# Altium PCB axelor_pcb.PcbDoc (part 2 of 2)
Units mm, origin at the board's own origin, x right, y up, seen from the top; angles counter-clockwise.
Board outline 74.68 x 44.83 mm, 4 copper layers (Top Layer, Int1 (GND), Int2 (PWR), Bottom Layer), stack 1.586 mm thick; 281 components, 64 nets, 713 pads, 300 vias.
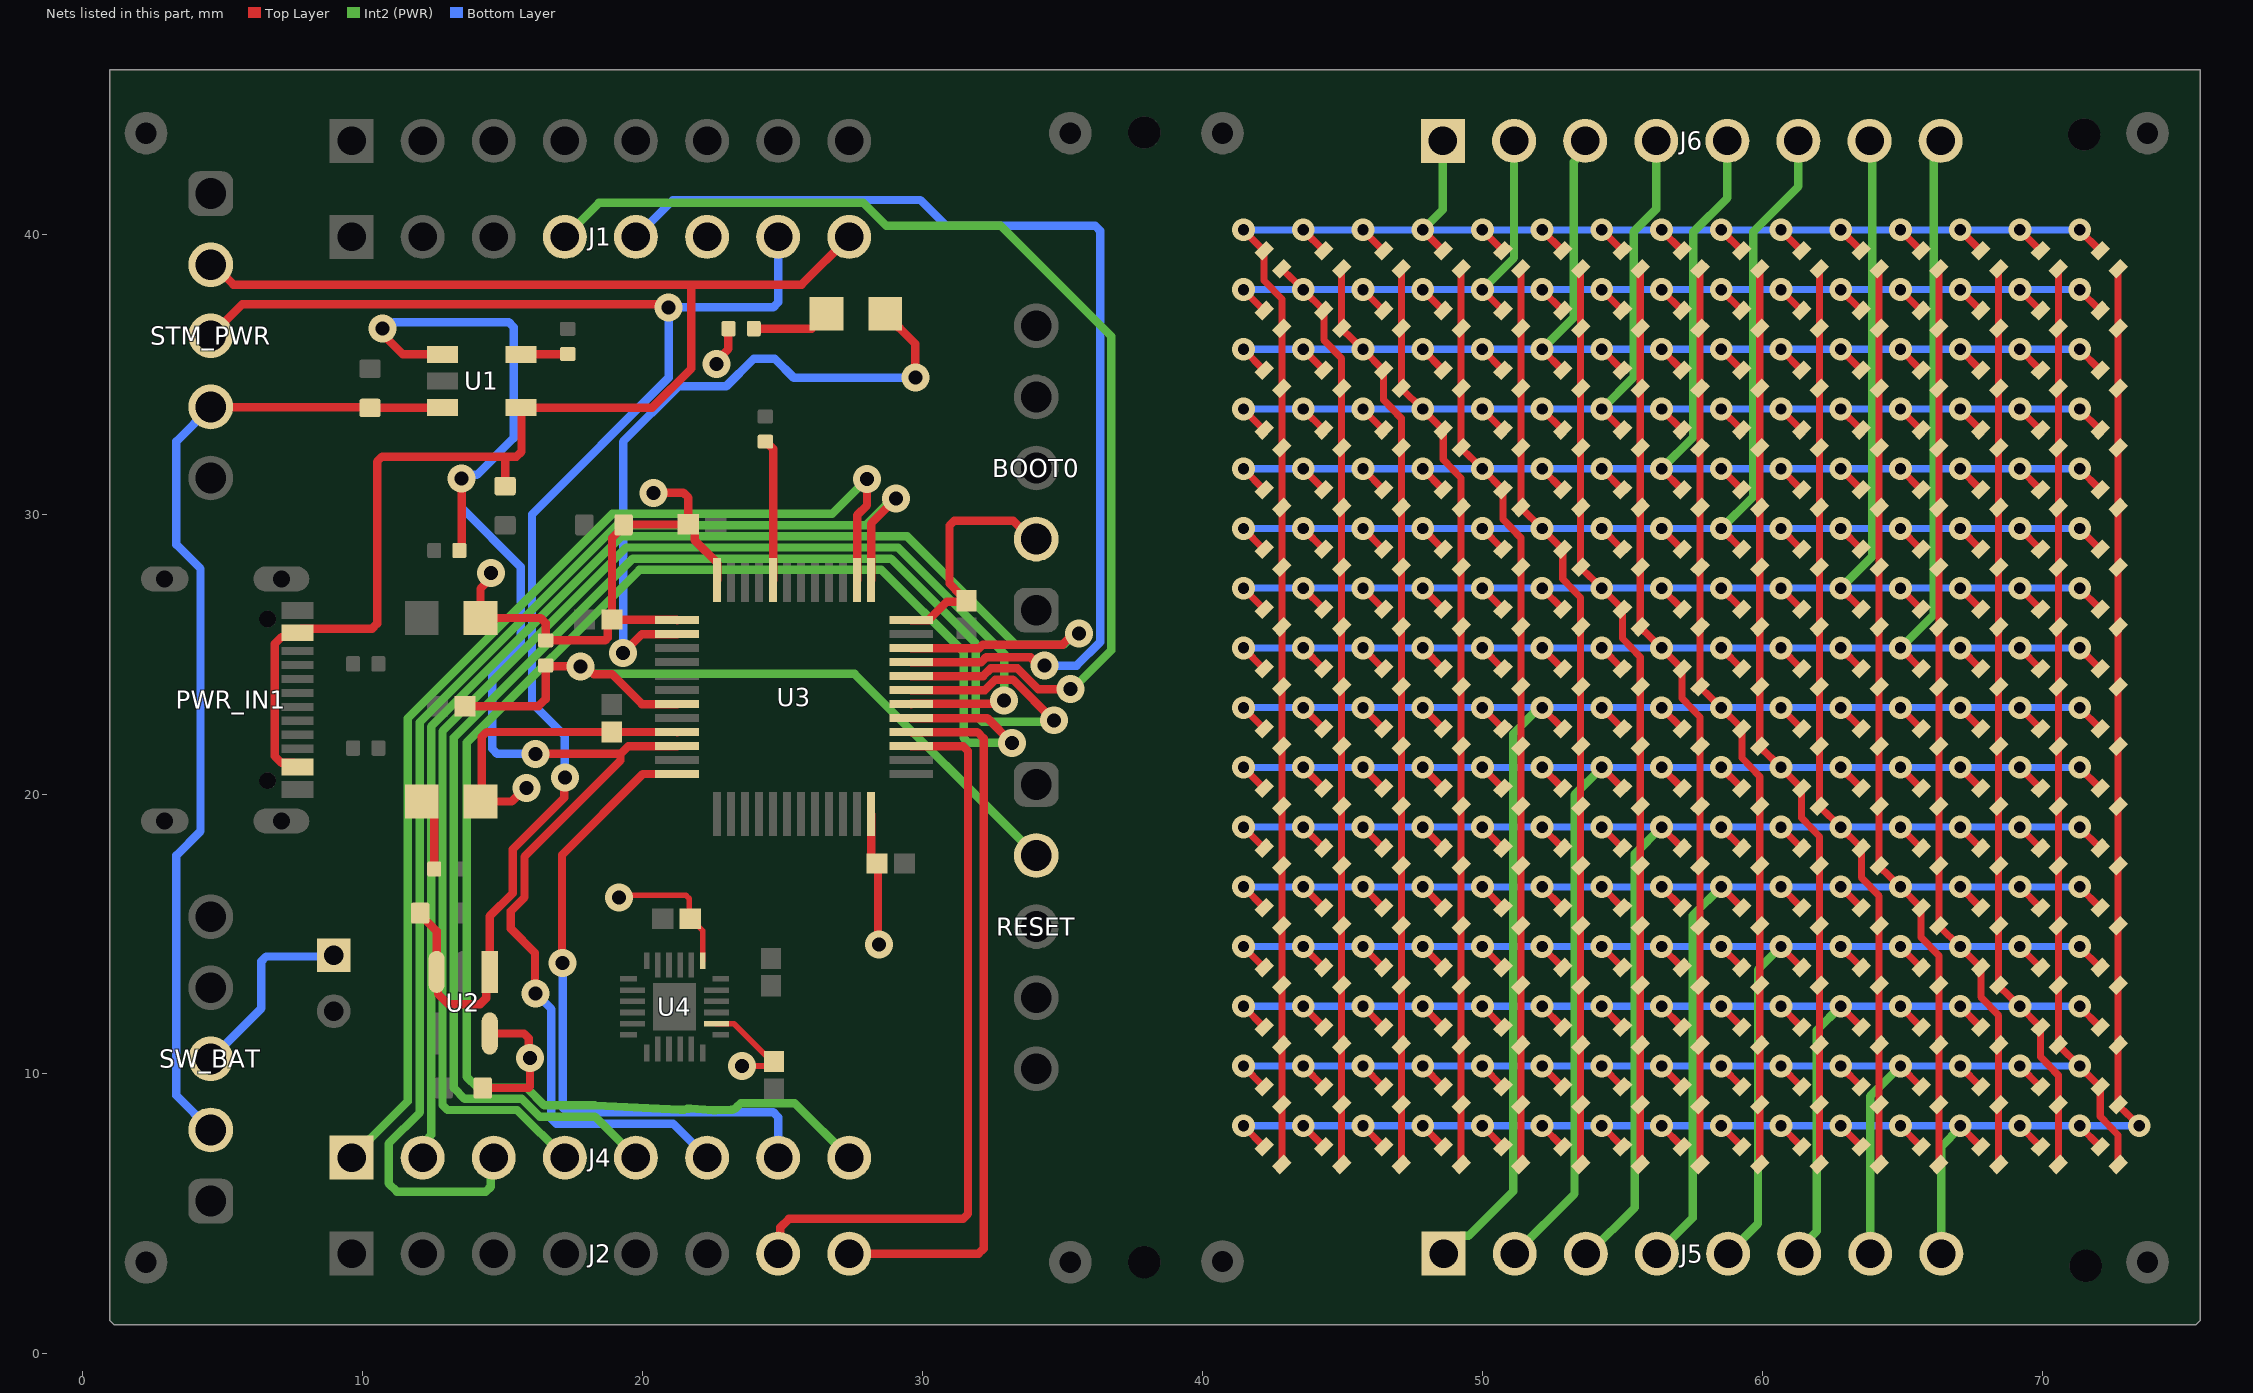
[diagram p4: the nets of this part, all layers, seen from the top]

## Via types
v1: diameter 0.813, hole 0.406, Top Layer to Bottom Layer, 241 vias
v2: diameter 1, hole 0.5, Top Layer to Bottom Layer, 55 vias
v3: diameter 0.5, hole 0.2, Top Layer to Bottom Layer, 4 vias

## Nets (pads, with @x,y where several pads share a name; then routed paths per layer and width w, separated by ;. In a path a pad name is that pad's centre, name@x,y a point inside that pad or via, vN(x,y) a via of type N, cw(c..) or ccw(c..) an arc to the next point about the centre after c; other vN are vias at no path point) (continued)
PB14: J2.7 U3.27 | length 26.5
  Top Layer w0.3: J2.7@24.841,3.581 24.917,3.658 24.917,4.521 25.222,4.826 31.447,4.826 31.623,5.002 31.623,21.54 31.447,21.716 U3.27@29.591,21.716
PB15: J2.8 U3.28 | length 25.8
  Top Layer w0.3: J2.8@27.381,3.581 32.006,3.581 32.182,3.757 32.182,21.99 31.956,22.216 U3.28@29.591,22.216
PIN1: D1.1 D2.1 D3.1 D4.1 D5.1 D6.1 D7.1 D8.1 D9.1 D10.1 D11.1 D12.1 D13.1 D14.1 D15.1 D16.2 D31.2 D46.2 D61.2 D76.2 D91.2 D106.2 D121.2 D136.2 D151.2 D166.2 D181.2 D196.2 D211.2 D226.2 J6.1 | length 81.9
  Top Layer w0.254: v1@41.465,40.145 D1.1@42.202,39.408 ; D1.1@42.202,39.42 42.202,38.353 42.838,37.693 D16.2@42.838,36.638 D31.2@42.838,34.505 D46.2@42.838,32.371 D61.2@42.838,30.237 D76.2@42.838,28.104 D91.2@42.838,25.97 D106.2@42.838,23.837 D121.2@42.838,21.703 D136.2@42.838,19.569 D151.2@42.838,17.436 D166.2@42.838,15.302 D181.2@42.838,13.169 D196.2@42.838,11.035 D211.2@42.838,8.901 D226.2@42.838,6.756 ; v1@43.599,40.145 D2.1@44.336,39.408 ; v1@45.733,40.145 D3.1@46.469,39.408 ; v1@47.866,40.145 D4.1@48.603,39.408 ; v1@50,40.145 D5.1@50.736,39.408 ; v1@52.133,40.145 D6.1@52.87,39.408 ; v1@54.267,40.145 D7.1@55.004,39.408 ; v1@56.401,40.145 D8.1@57.137,39.408 ; v1@58.534,40.145 D9.1@59.271,39.408 ; v1@60.668,40.145 D10.1@61.404,39.408 ; v1@62.801,40.145 D11.1@63.538,39.408 ; v1@64.935,40.145 D12.1@65.672,39.408 ; v1@67.069,40.145 D13.1@67.805,39.408 ; v1@69.202,40.145 D14.1@69.939,39.408 ; v1@71.336,40.145 D15.1@72.072,39.408
  Int2 (PWR) w0.3: v1(47.866,40.157) 48.59,40.881 J6.1@48.59,43.332
  Bottom Layer w0.254: v1(41.465,40.157) v1(43.599,40.157) v1(45.733,40.157) v1(47.866,40.157) v1(50,40.157) v1(52.133,40.157) v1(54.267,40.157) v1(56.401,40.157) v1(58.534,40.157) v1(60.668,40.157) v1(62.801,40.157) v1(64.935,40.157) v1(67.069,40.157) v1(69.202,40.157) v1(71.336,40.157)
PIN2: D1.2 D16.1 D17.1 D18.1 D19.1 D20.1 D21.1 D22.1 D23.1 D24.1 D25.1 D26.1 D27.1 D28.1 D29.1 D30.1 D32.2 D47.2 D62.2 D77.2 D92.2 D107.2 D122.2 D137.2 D152.2 D167.2 D182.2 D197.2 D212.2 D227.2 J6.2 | length 83.1
  Top Layer w0.254: v1@41.465,38.011 D16.1@42.202,37.274 ; D1.2@42.838,38.76 v1(43.599,38.023) ; v1@43.599,38.011 D17.1@44.336,37.274 ; D17.1@44.336,37.287 44.336,36.22 44.972,35.559 D32.2@44.972,34.505 D47.2@44.972,32.371 D62.2@44.972,30.237 D77.2@44.972,28.104 D92.2@44.972,25.97 D107.2@44.972,23.837 D122.2@44.972,21.703 D137.2@44.972,19.569 D152.2@44.972,17.436 D167.2@44.972,15.302 D182.2@44.972,13.169 D197.2@44.972,11.035 D212.2@44.972,8.901 D227.2@44.972,6.756 ; v1@45.733,38.011 D18.1@46.469,37.274 ; v1@47.866,38.011 D19.1@48.603,37.274 ; v1@50,38.011 D20.1@50.736,37.274 ; v1@52.133,38.011 D21.1@52.87,37.274 ; v1@54.267,38.011 D22.1@55.004,37.274 ; v1@56.401,38.011 D23.1@57.137,37.274 ; v1@58.534,38.011 D24.1@59.271,37.274 ; v1@60.668,38.011 D25.1@61.404,37.274 ; v1@62.801,38.011 D26.1@63.538,37.274 ; v1@64.935,38.011 D27.1@65.672,37.274 ; v1@67.069,38.011 D28.1@67.805,37.274 ; v1@69.202,38.011 D29.1@69.939,37.274 ; v1@71.336,38.011 D30.1@72.072,37.274
  Int2 (PWR) w0.3: v1(50,38.023) 51.13,39.153 J6.2@51.13,43.332
  Bottom Layer w0.254: v1(41.465,38.023) v1(43.599,38.023) v1(45.733,38.023) v1(47.866,38.023) v1(50,38.023) v1(52.133,38.023) v1(54.267,38.023) v1(56.401,38.023) v1(58.534,38.023) v1(60.668,38.023) v1(62.801,38.023) v1(64.935,38.023) v1(67.069,38.023) v1(69.202,38.023) v1(71.336,38.023)
PIN3: D2.2 D17.2 D31.1 D32.1 D33.1 D34.1 D35.1 D36.1 D37.1 D38.1 D39.1 D40.1 D41.1 D42.1 D43.1 D44.1 D45.1 D48.2 D63.2 D78.2 D93.2 D108.2 D123.2 D138.2 D153.2 D168.2 D183.2 D198.2 D213.2 D228.2 J6.3 | length 85.5
  Top Layer w0.254: v1@41.465,35.877 D31.1@42.202,35.141 ; v1@43.599,35.877 D32.1@44.336,35.141 ; D2.2@44.972,38.76 44.972,36.626 v1(45.733,35.89) ; v1@45.733,35.877 D33.1@46.469,35.141 ; D33.1@46.469,35.153 46.469,34.086 47.106,33.426 D48.2@47.106,32.371 D63.2@47.106,30.237 D78.2@47.106,28.104 D93.2@47.106,25.97 D108.2@47.106,23.837 D123.2@47.106,21.703 D138.2@47.106,19.569 D153.2@47.106,17.436 D168.2@47.106,15.302 D183.2@47.106,13.169 D198.2@47.106,11.035 D213.2@47.106,8.901 D228.2@47.106,6.756 ; v1@47.866,35.877 D34.1@48.603,35.141 ; v1@50,35.877 D35.1@50.736,35.141 ; v1@52.133,35.877 D36.1@52.87,35.141 ; v1@54.267,35.877 D37.1@55.004,35.141 ; v1@56.401,35.877 D38.1@57.137,35.141 ; v1@58.534,35.877 D39.1@59.271,35.141 ; v1@60.668,35.877 D40.1@61.404,35.141 ; v1@62.801,35.877 D41.1@63.538,35.141 ; v1@64.935,35.877 D42.1@65.672,35.141 ; v1@67.069,35.877 D43.1@67.805,35.141 ; v1@69.202,35.877 D44.1@69.939,35.141 ; v1@71.336,35.877 D45.1@72.072,35.141
  Int2 (PWR) w0.3: v1@41.389,35.966 v1(41.465,35.89) ; v1(52.133,35.89) 53.262,37.018 53.262,42.58 53.67,42.989 J6.3@53.67,43.332
  Bottom Layer w0.254: v1(41.465,35.89) v1(43.599,35.89) v1(45.733,35.89) v1(47.866,35.89) v1(50,35.89) v1(52.133,35.89) v1(54.267,35.89) v1(56.401,35.89) v1(58.534,35.89) v1(60.668,35.89) v1(62.801,35.89) v1(64.935,35.89) v1(67.069,35.89) v1(69.202,35.89) v1(71.336,35.89)
PIN4: D3.2 D18.2 D33.2 D46.1 D47.1 D48.1 D49.1 D50.1 D51.1 D52.1 D53.1 D54.1 D55.1 D56.1 D57.1 D58.1 D59.1 D60.1 D64.2 D79.2 D94.2 D109.2 D124.2 D139.2 D154.2 D169.2 D184.2 D199.2 D214.2 D229.2 J6.4 | length 87.7
  Top Layer w0.254: v1@41.465,33.744 D46.1@42.202,33.007 ; v1@43.599,33.744 D47.1@44.336,33.007 ; v1@45.733,33.744 D48.1@46.469,33.007 ; D3.2@47.106,38.76 D18.2@47.106,36.638 47.106,34.493 v1(47.866,33.756) ; v1@47.866,33.744 D49.1@48.603,33.007 ; D49.1@48.603,33.019 48.603,31.953 49.239,31.292 D64.2@49.239,30.237 D79.2@49.239,28.104 D94.2@49.239,25.97 D109.2@49.239,23.837 D124.2@49.239,21.703 D139.2@49.239,19.569 D154.2@49.239,17.436 D169.2@49.239,15.302 D184.2@49.239,13.169 D199.2@49.239,11.035 D214.2@49.239,8.901 D229.2@49.239,6.756 ; v1@50,33.744 D50.1@50.736,33.007 ; v1@52.133,33.744 D51.1@52.87,33.007 ; v1@54.267,33.744 D52.1@55.004,33.007 ; v1@56.401,33.744 D53.1@57.137,33.007 ; v1@58.534,33.744 D54.1@59.271,33.007 ; v1@60.668,33.744 D55.1@61.404,33.007 ; v1@62.801,33.744 D56.1@63.538,33.007 ; v1@64.935,33.744 D57.1@65.672,33.007 ; v1@67.069,33.744 D58.1@67.805,33.007 ; v1@69.202,33.744 D59.1@69.939,33.007 ; v1@71.336,33.744 D60.1@72.072,33.007
  Int2 (PWR) w0.3: v1(54.267,33.756) 55.407,34.896 55.407,40.091 56.21,40.894 J6.4@56.21,43.332
  Bottom Layer w0.254: v1(41.465,33.756) v1(43.599,33.756) v1(45.733,33.756) v1(47.866,33.756) v1(50,33.756) v1(52.133,33.756) v1(54.267,33.756) v1(56.401,33.756) v1(58.534,33.756) v1(60.668,33.756) v1(62.801,33.756) v1(64.935,33.756) v1(67.069,33.756) v1(69.202,33.756) v1(71.336,33.756)
PIN5: D4.2 D19.2 D34.2 D49.2 D61.1 D62.1 D63.1 D64.1 D65.1 D66.1 D67.1 D68.1 D69.1 D70.1 D71.1 D72.1 D73.1 D74.1 D75.1 D80.2 D95.2 D110.2 D125.2 D140.2 D155.2 D170.2 D185.2 D200.2 D215.2 D230.2 J6.5 | length 90
  Top Layer w0.254: v1@41.465,31.61 D61.1@42.202,30.874 ; v1@43.599,31.61 D62.1@44.336,30.874 ; v1@45.733,31.61 D63.1@46.469,30.874 ; v1@47.866,31.61 D64.1@48.603,30.874 ; D4.2@49.239,38.76 D19.2@49.239,36.638 D34.2@49.239,34.505 49.239,32.359 v1(50,31.622) ; v1@50,31.61 D65.1@50.736,30.874 ; D65.1@50.736,30.886 50.736,29.819 51.373,29.159 D80.2@51.373,28.104 D95.2@51.373,25.97 D110.2@51.373,23.837 D125.2@51.373,21.703 D140.2@51.373,19.569 D155.2@51.373,17.436 D170.2@51.373,15.302 D185.2@51.373,13.169 D200.2@51.373,11.035 D215.2@51.373,8.901 D230.2@51.373,6.756 ; v1@52.133,31.61 D66.1@52.87,30.874 ; v1@54.267,31.61 D67.1@55.004,30.874 ; v1@56.401,31.61 D68.1@57.137,30.874 ; v1@58.534,31.61 D69.1@59.271,30.874 ; v1@60.668,31.61 D70.1@61.404,30.874 ; v1@62.801,31.61 D71.1@63.538,30.874 ; v1@64.935,31.61 D72.1@65.672,30.874 ; v1@67.069,31.61 D73.1@67.805,30.874 ; v1@69.202,31.61 D74.1@69.939,30.874 ; v1@71.336,31.61 D75.1@72.072,30.874
  Int2 (PWR) w0.3: v1(56.401,31.622) 57.538,32.76 57.538,40.089 58.75,41.301 J6.5@58.75,43.332
  Bottom Layer w0.254: v1(41.465,31.622) v1(43.599,31.622) v1(45.733,31.622) v1(47.866,31.622) v1(50,31.622) v1(52.133,31.622) v1(54.267,31.622) v1(56.401,31.622) v1(58.534,31.622) v1(60.668,31.622) v1(62.801,31.622) v1(64.935,31.622) v1(67.069,31.622) v1(69.202,31.622) v1(71.336,31.622)
PIN6: D5.2 D20.2 D35.2 D50.2 D65.2 D76.1 D77.1 D78.1 D79.1 D80.1 D81.1 D82.1 D83.1 D84.1 D85.1 D86.1 D87.1 D88.1 D89.1 D90.1 D96.2 D111.2 D126.2 D141.2 D156.2 D171.2 D186.2 D201.2 D216.2 D231.2 J6.6 | length 92.3
  Top Layer w0.254: v1@41.465,29.477 D76.1@42.202,28.74 ; v1@43.599,29.477 D77.1@44.336,28.74 ; v1@45.733,29.477 D78.1@46.469,28.74 ; v1@47.866,29.477 D79.1@48.603,28.74 ; v1@50,29.477 D80.1@50.736,28.74 ; D5.2@51.373,38.76 D20.2@51.373,36.638 D35.2@51.373,34.505 D50.2@51.373,32.371 51.373,30.225 v1(52.133,29.489) ; v1@52.133,29.477 D81.1@52.87,28.74 ; D81.1@52.87,28.752 52.87,27.685 53.506,27.025 D96.2@53.506,25.97 D111.2@53.506,23.837 D126.2@53.506,21.703 D141.2@53.506,19.569 D156.2@53.506,17.436 D171.2@53.506,15.302 D186.2@53.506,13.169 D201.2@53.506,11.035 D216.2@53.506,8.901 D231.2@53.506,6.756 ; v1@54.267,29.477 D82.1@55.004,28.74 ; v1@56.401,29.477 D83.1@57.137,28.74 ; v1@58.534,29.477 D84.1@59.271,28.74 ; v1@60.668,29.477 D85.1@61.404,28.74 ; v1@62.801,29.477 D86.1@63.538,28.74 ; v1@64.935,29.477 D87.1@65.672,28.74 ; v1@67.069,29.477 D88.1@67.805,28.74 ; v1@69.202,29.477 D89.1@69.939,28.74 ; v1@71.336,29.477 D90.1@72.072,28.74
  Int2 (PWR) w0.3: v1(58.534,29.489) 59.678,30.632 59.678,40.095 61.29,41.707 J6.6@61.29,43.332
  Bottom Layer w0.254: v1(41.465,29.489) v1(43.599,29.489) v1(45.733,29.489) v1(47.866,29.489) v1(50,29.489) v1(52.133,29.489) v1(54.267,29.489) v1(56.401,29.489) v1(58.534,29.489) v1(60.668,29.489) v1(62.801,29.489) v1(64.935,29.489) v1(67.069,29.489) v1(69.202,29.489) v1(71.336,29.489)
PIN7: D6.2 D21.2 D36.2 D51.2 D66.2 D81.2 D91.1 D92.1 D93.1 D94.1 D95.1 D96.1 D97.1 D98.1 D99.1 D100.1 D101.1 D102.1 D103.1 D104.1 D105.1 D112.2 D127.2 D142.2 D157.2 D172.2 D187.2 D202.2 D217.2 D232.2 J6.7 | length 93.8
  Top Layer w0.254: v1@41.465,27.343 D91.1@42.202,26.607 ; v1@43.599,27.343 D92.1@44.336,26.607 ; v1@45.733,27.343 D93.1@46.469,26.607 ; v1@47.866,27.343 D94.1@48.603,26.607 ; v1@50,27.343 D95.1@50.736,26.607 ; v1@52.133,27.343 D96.1@52.87,26.607 ; D6.2@53.506,38.76 D21.2@53.506,36.638 D36.2@53.506,34.505 D51.2@53.506,32.371 D66.2@53.506,30.237 53.506,28.092 v1(54.267,27.355) ; v1@54.267,27.343 D97.1@55.004,26.607 ; D97.1@55.004,26.619 55.004,25.552 55.64,24.891 D112.2@55.64,23.837 D127.2@55.64,21.703 D142.2@55.64,19.569 D157.2@55.64,17.436 D172.2@55.64,15.302 D187.2@55.64,13.169 D202.2@55.64,11.035 D217.2@55.64,8.901 D232.2@55.64,6.756 ; v1@56.401,27.343 D98.1@57.137,26.607 ; v1@58.534,27.343 D99.1@59.271,26.607 ; v1@60.668,27.343 D100.1@61.404,26.607 ; v1@62.801,27.343 D101.1@63.538,26.607 ; v1@64.935,27.343 D102.1@65.672,26.607 ; v1@67.069,27.343 D103.1@67.805,26.607 ; v1@69.202,27.343 D104.1@69.939,26.607 ; v1@71.336,27.343 D105.1@72.072,26.607
  Int2 (PWR) w0.3: v1(62.801,27.355) 63.925,28.479 63.925,43.237 J6.7@63.83,43.332
  Bottom Layer w0.254: v1(41.465,27.355) v1(43.599,27.355) v1(45.733,27.355) v1(47.866,27.355) v1(50,27.355) v1(52.133,27.355) v1(54.267,27.355) v1(56.401,27.355) v1(58.534,27.355) v1(60.668,27.355) v1(62.801,27.355) v1(64.935,27.355) v1(67.069,27.355) v1(69.202,27.355) v1(71.336,27.355)
PIN8: D7.2 D22.2 D37.2 D52.2 D67.2 D82.2 D97.2 D106.1 D107.1 D108.1 D109.1 D110.1 D111.1 D112.1 D113.1 D114.1 D115.1 D116.1 D117.1 D118.1 D119.1 D120.1 D128.2 D143.2 D158.2 D173.2 D188.2 D203.2 D218.2 D233.2 J6.8 | length 96
  Top Layer w0.254: v1@41.465,25.209 D106.1@42.202,24.473 ; v1@43.599,25.209 D107.1@44.336,24.473 ; v1@45.733,25.209 D108.1@46.469,24.473 ; v1@47.866,25.209 D109.1@48.603,24.473 ; v1@50,25.209 D110.1@50.736,24.473 ; v1@52.133,25.209 D111.1@52.87,24.473 ; v1@54.267,25.209 D112.1@55.004,24.473 ; D7.2@55.64,38.76 D22.2@55.64,36.638 D37.2@55.64,34.505 D52.2@55.64,32.371 D67.2@55.64,30.237 D82.2@55.64,28.104 55.64,25.958 v1(56.401,25.222) ; v1@56.401,25.209 D113.1@57.137,24.473 ; D113.1@57.137,24.485 57.137,23.418 57.774,22.758 D128.2@57.774,21.703 D143.2@57.774,19.569 D158.2@57.774,17.436 D173.2@57.774,15.302 D188.2@57.774,13.169 D203.2@57.774,11.035 D218.2@57.774,8.901 D233.2@57.774,6.756 ; v1@58.534,25.209 D114.1@59.271,24.473 ; v1@60.668,25.209 D115.1@61.404,24.473 ; v1@62.801,25.209 D116.1@63.538,24.473 ; v1@64.935,25.209 D117.1@65.672,24.473 ; v1@67.069,25.209 D118.1@67.805,24.473 ; v1@69.202,25.209 D119.1@69.939,24.473 ; v1@71.336,25.209 D120.1@72.072,24.473
  Int2 (PWR) w0.3: v1(64.935,25.222) 66.127,26.414 66.127,43.089 J6.8@66.37,43.332
  Bottom Layer w0.254: v1(41.465,25.222) v1(43.599,25.222) v1(45.733,25.222) v1(47.866,25.222) v1(50,25.222) v1(52.133,25.222) v1(54.267,25.222) v1(56.401,25.222) v1(58.534,25.222) v1(60.668,25.222) v1(62.801,25.222) v1(64.935,25.222) v1(67.069,25.222) v1(69.202,25.222) v1(71.336,25.222)
PIN9: D8.2 D23.2 D38.2 D53.2 D68.2 D83.2 D98.2 D113.2 D121.1 D122.1 D123.1 D124.1 D125.1 D126.1 D127.1 D128.1 D129.1 D130.1 D131.1 D132.1 D133.1 D134.1 D135.1 D144.2 D159.2 D174.2 D189.2 D204.2 D219.2 D234.2 J5.1 | length 98.5
  Top Layer w0.254: v1@41.465,23.076 D121.1@42.202,22.339 ; v1@43.599,23.076 D122.1@44.336,22.339 ; v1@45.733,23.076 D123.1@46.469,22.339 ; v1@47.866,23.076 D124.1@48.603,22.339 ; v1@50,23.076 D125.1@50.736,22.339 ; v1@52.133,23.076 D126.1@52.87,22.339 ; v1@54.267,23.076 D127.1@55.004,22.339 ; v1@56.401,23.076 D128.1@57.137,22.339 ; D8.2@57.774,38.76 D23.2@57.774,36.638 D38.2@57.774,34.505 D53.2@57.774,32.371 D68.2@57.774,30.237 D83.2@57.774,28.104 D98.2@57.774,25.97 57.774,23.825 v1(58.534,23.088) ; v1@58.534,23.076 D129.1@59.271,22.339 ; D129.1@59.271,22.351 59.271,21.285 59.907,20.624 D144.2@59.907,19.569 D159.2@59.907,17.436 D174.2@59.907,15.302 D189.2@59.907,13.169 D204.2@59.907,11.035 D219.2@59.907,8.901 D234.2@59.907,6.756 ; v1@60.668,23.076 D130.1@61.404,22.339 ; v1@62.801,23.076 D131.1@63.538,22.339 ; v1@64.935,23.076 D132.1@65.672,22.339 ; v1@67.069,23.076 D133.1@67.805,22.339 ; v1@69.202,23.076 D134.1@69.939,22.339 ; v1@71.336,23.076 D135.1@72.072,22.339
  Int2 (PWR) w0.3: J5.1@48.616,3.581 49.251,4.216 49.505,4.216 51.105,5.817 51.105,22.161 52.032,23.088 v1(52.133,23.088)
  Bottom Layer w0.254: v1(41.465,23.088) v1(43.599,23.088) v1(45.733,23.088) v1(47.866,23.088) v1(50,23.088) v1(52.133,23.088) v1(54.267,23.088) v1(56.401,23.088) v1(58.534,23.088) v1(60.668,23.088) v1(62.801,23.088) v1(64.935,23.088) v1(67.069,23.088) v1(69.202,23.088) v1(71.336,23.088)
PIN10: D9.2 D24.2 D39.2 D54.2 D69.2 D84.2 D99.2 D114.2 D129.2 D136.1 D137.1 D138.1 D139.1 D140.1 D141.1 D142.1 D143.1 D144.1 D145.1 D146.1 D147.1 D148.1 D149.1 D150.1 D160.2 D175.2 D190.2 D205.2 D220.2 D235.2 J5.2 | length 96
  Top Layer w0.254: v1@41.465,20.942 D136.1@42.202,20.206 ; v1@43.599,20.942 D137.1@44.336,20.206 ; v1@45.733,20.942 D138.1@46.469,20.206 ; v1@47.866,20.942 D139.1@48.603,20.206 ; v1@50,20.942 D140.1@50.736,20.206 ; v1@52.133,20.942 D141.1@52.87,20.206 ; v1@54.267,20.942 D142.1@55.004,20.206 ; v1@56.401,20.942 D143.1@57.137,20.206 ; v1@58.534,20.942 D144.1@59.271,20.206 ; D9.2@59.907,38.76 D24.2@59.907,36.638 D39.2@59.907,34.505 D54.2@59.907,32.371 D69.2@59.907,30.237 D84.2@59.907,28.104 D99.2@59.907,25.97 D114.2@59.907,23.837 59.907,21.691 v1(60.668,20.954) ; v1@60.668,20.942 D145.1@61.404,20.206 ; D145.1@61.404,20.218 61.404,19.151 62.041,18.491 D160.2@62.041,17.436 D175.2@62.041,15.302 D190.2@62.041,13.169 D205.2@62.041,11.035 D220.2@62.041,8.901 D235.2@62.041,6.756 ; v1@62.801,20.942 D146.1@63.538,20.206 ; v1@64.935,20.942 D147.1@65.672,20.206 ; v1@67.069,20.942 D148.1@67.805,20.206 ; v1@69.202,20.942 D149.1@69.939,20.206 ; v1@71.336,20.942 D150.1@72.072,20.206
  Int2 (PWR) w0.3: J5.2@51.156,3.581 53.289,5.715 53.289,19.976 v1(54.267,20.954)
  Bottom Layer w0.254: v1(41.465,20.954) v1(43.599,20.954) v1(45.733,20.954) v1(47.866,20.954) v1(50,20.954) v1(52.133,20.954) v1(54.267,20.954) v1(56.401,20.954) v1(58.534,20.954) v1(60.668,20.954) v1(62.801,20.954) v1(64.935,20.954) v1(67.069,20.954) v1(69.202,20.954) v1(71.336,20.954)
PIN11: D10.2 D25.2 D40.2 D55.2 D70.2 D85.2 D100.2 D115.2 D130.2 D145.2 D151.1 D152.1 D153.1 D154.1 D155.1 D156.1 D157.1 D158.1 D159.1 D160.1 D161.1 D162.1 D163.1 D164.1 D165.1 D176.2 D191.2 D206.2 D221.2 D236.2 J5.3 | length 93.7
  Top Layer w0.254: v1@41.465,18.809 D151.1@42.202,18.072 ; v1@43.599,18.809 D152.1@44.336,18.072 ; v1@45.733,18.809 D153.1@46.469,18.072 ; v1@47.866,18.809 D154.1@48.603,18.072 ; v1@50,18.809 D155.1@50.736,18.072 ; v1@52.133,18.809 D156.1@52.87,18.072 ; v1@54.267,18.809 D157.1@55.004,18.072 ; v1@56.401,18.809 D158.1@57.137,18.072 ; v1@58.534,18.809 D159.1@59.271,18.072 ; v1@60.668,18.809 D160.1@61.404,18.072 ; D10.2@62.041,38.76 D25.2@62.041,36.638 D40.2@62.041,34.505 D55.2@62.041,32.371 D70.2@62.041,30.237 D85.2@62.041,28.104 D100.2@62.041,25.97 D115.2@62.041,23.837 D130.2@62.041,21.703 62.041,19.557 v1(62.801,18.821) ; v1@62.801,18.809 D161.1@63.538,18.072 ; D161.1@63.538,18.084 63.538,17.017 64.174,16.357 D176.2@64.174,15.302 D191.2@64.174,13.169 D206.2@64.174,11.035 D221.2@64.174,8.901 D236.2@64.174,6.756 ; v1@64.935,18.809 D162.1@65.672,18.072 ; v1@67.069,18.809 D163.1@67.805,18.072 ; v1@69.202,18.809 D164.1@69.939,18.072 ; v1@71.336,18.809 D165.1@72.072,18.072
  Int2 (PWR) w0.3: J5.3@53.797,3.581 55.448,5.232 55.448,17.868 v1(56.401,18.821)
  Bottom Layer w0.254: v1(41.465,18.821) v1(43.599,18.821) v1(45.733,18.821) v1(47.866,18.821) v1(50,18.821) v1(52.133,18.821) v1(54.267,18.821) v1(56.401,18.821) v1(58.534,18.821) v1(60.668,18.821) v1(62.801,18.821) v1(64.935,18.821) v1(67.069,18.821) v1(69.202,18.821) v1(71.336,18.821)
PIN12: D11.2 D26.2 D41.2 D56.2 D71.2 D86.2 D101.2 D116.2 D131.2 D146.2 D161.2 D166.1 D167.1 D168.1 D169.1 D170.1 D171.1 D172.1 D173.1 D174.1 D175.1 D176.1 D177.1 D178.1 D179.1 D180.1 D192.2 D207.2 D222.2 D237.2 J5.4 | length 91.4
  Top Layer w0.254: v1@41.465,16.675 D166.1@42.202,15.938 ; v1@43.599,16.675 D167.1@44.336,15.938 ; v1@45.733,16.675 D168.1@46.469,15.938 ; v1@47.866,16.675 D169.1@48.603,15.938 ; v1@50,16.675 D170.1@50.736,15.938 ; v1@52.133,16.675 D171.1@52.87,15.938 ; v1@54.267,16.675 D172.1@55.004,15.938 ; v1@56.401,16.675 D173.1@57.137,15.938 ; v1@58.534,16.675 D174.1@59.271,15.938 ; v1@60.668,16.675 D175.1@61.404,15.938 ; v1@62.801,16.675 D176.1@63.538,15.938 ; D11.2@64.174,38.76 D26.2@64.174,36.638 D41.2@64.174,34.505 D56.2@64.174,32.371 D71.2@64.174,30.237 D86.2@64.174,28.104 D101.2@64.174,25.97 D116.2@64.174,23.837 D131.2@64.174,21.703 D146.2@64.174,19.569 64.174,17.424 v1(64.935,16.687) ; v1@64.935,16.675 D177.1@65.672,15.938 ; D177.1@65.672,15.951 65.672,14.884 66.308,14.223 D192.2@66.308,13.169 D207.2@66.308,11.035 D222.2@66.308,8.901 D237.2@66.308,6.756 ; v1@67.069,16.675 D178.1@67.805,15.938 ; v1@69.202,16.675 D179.1@69.939,15.938 ; v1@71.336,16.675 D180.1@72.072,15.938
  Int2 (PWR) w0.3: J5.4@56.236,3.581 57.508,4.854 57.508,15.661 v1(58.534,16.687)
  Bottom Layer w0.254: v1(41.465,16.687) v1(43.599,16.687) v1(45.733,16.687) v1(47.866,16.687) v1(50,16.687) v1(52.133,16.687) v1(54.267,16.687) v1(56.401,16.687) v1(58.534,16.687) v1(60.668,16.687) v1(62.801,16.687) v1(64.935,16.687) v1(67.069,16.687) v1(69.202,16.687) v1(71.336,16.687)
PIN13: D12.2 D27.2 D42.2 D57.2 D72.2 D87.2 D102.2 D117.2 D132.2 D147.2 D162.2 D177.2 D181.1 D182.1 D183.1 D184.1 D185.1 D186.1 D187.1 D188.1 D189.1 D190.1 D191.1 D192.1 D193.1 D194.1 D195.1 D208.2 D223.2 D238.2 J5.5 | length 89.1
  Top Layer w0.254: v1@41.465,14.541 D181.1@42.202,13.805 ; v1@43.599,14.541 D182.1@44.336,13.805 ; v1@45.733,14.541 D183.1@46.469,13.805 ; v1@47.866,14.541 D184.1@48.603,13.805 ; v1@50,14.541 D185.1@50.736,13.805 ; v1@52.133,14.541 D186.1@52.87,13.805 ; v1@54.267,14.541 D187.1@55.004,13.805 ; v1@56.401,14.541 D188.1@57.137,13.805 ; v1@58.534,14.541 D189.1@59.271,13.805 ; v1@60.668,14.541 D190.1@61.404,13.805 ; v1@62.801,14.541 D191.1@63.538,13.805 ; v1@64.935,14.541 D192.1@65.672,13.805 ; D12.2@66.308,38.76 D27.2@66.308,36.638 D42.2@66.308,34.505 D57.2@66.308,32.371 D72.2@66.308,30.237 D87.2@66.308,28.104 D102.2@66.308,25.97 D117.2@66.308,23.837 D132.2@66.308,21.703 D147.2@66.308,19.569 D162.2@66.308,17.436 66.308,15.29 v1(67.069,14.554) ; v1@67.069,14.541 D193.1@67.805,13.805 ; D193.1@67.805,13.817 67.805,12.75 68.442,12.09 D208.2@68.442,11.035 D223.2@68.442,8.901 D238.2@68.442,6.756 ; v1@69.202,14.541 D194.1@69.939,13.805 ; v1@71.336,14.541 D195.1@72.072,13.805
  Int2 (PWR) w0.3: J5.5@58.776,3.581 59.845,4.651 59.845,13.731 v1(60.668,14.554)
  Bottom Layer w0.254: v1(41.465,14.554) v1(43.599,14.554) v1(45.733,14.554) v1(47.866,14.554) v1(50,14.554) v1(52.133,14.554) v1(54.267,14.554) v1(56.401,14.554) v1(58.534,14.554) v1(60.668,14.554) v1(62.801,14.554) v1(64.935,14.554) v1(67.069,14.554) v1(69.202,14.554) v1(71.336,14.554)
PIN14: D13.2 D28.2 D43.2 D58.2 D73.2 D88.2 D103.2 D118.2 D133.2 D148.2 D163.2 D178.2 D193.2 D196.1 D197.1 D198.1 D199.1 D200.1 D201.1 D202.1 D203.1 D204.1 D205.1 D206.1 D207.1 D208.1 D209.1 D210.1 D224.2 D239.2 J5.6 | length 86.8
  Top Layer w0.254: v1@41.465,12.408 D196.1@42.202,11.671 ; v1@43.599,12.408 D197.1@44.336,11.671 ; v1@45.733,12.408 D198.1@46.469,11.671 ; v1@47.866,12.408 D199.1@48.603,11.671 ; v1@50,12.408 D200.1@50.736,11.671 ; v1@52.133,12.408 D201.1@52.87,11.671 ; v1@54.267,12.408 D202.1@55.004,11.671 ; v1@56.401,12.408 D203.1@57.137,11.671 ; v1@58.534,12.408 D204.1@59.271,11.671 ; v1@60.668,12.408 D205.1@61.404,11.671 ; v1@62.801,12.408 D206.1@63.538,11.671 ; v1@64.935,12.408 D207.1@65.672,11.671 ; v1@67.069,12.408 D208.1@67.805,11.671 ; D13.2@68.442,38.76 D28.2@68.442,36.638 D43.2@68.442,34.505 D58.2@68.442,32.371 D73.2@68.442,30.237 D88.2@68.442,28.104 D103.2@68.442,25.97 D118.2@68.442,23.837 D133.2@68.442,21.703 D148.2@68.442,19.569 D163.2@68.442,17.436 D178.2@68.442,15.302 68.442,13.157 v1(69.202,12.42) ; v1@69.202,12.408 D209.1@69.939,11.671 ; D209.1@69.939,11.683 69.939,10.617 70.575,9.956 D224.2@70.575,8.901 D239.2@70.575,6.756 ; v1@71.336,12.408 D210.1@72.072,11.671
  Int2 (PWR) w0.3: J5.6@61.316,3.581 61.316,3.757 61.951,4.392 61.951,11.569 v1(62.801,12.42)
  Bottom Layer w0.254: v1(41.465,12.42) v1(43.599,12.42) v1(45.733,12.42) v1(47.866,12.42) v1(50,12.42) v1(52.133,12.42) v1(54.267,12.42) v1(56.401,12.42) v1(58.534,12.42) v1(60.668,12.42) v1(62.801,12.42) v1(64.935,12.42) v1(67.069,12.42) v1(69.202,12.42) v1(71.336,12.42)
PIN15: D14.2 D29.2 D44.2 D59.2 D74.2 D89.2 D104.2 D119.2 D134.2 D149.2 D164.2 D179.2 D194.2 D209.2 D211.1 D212.1 D213.1 D214.1 D215.1 D216.1 D217.1 D218.1 D219.1 D220.1 D221.1 D222.1 D223.1 D224.1 D225.1 D240.2 J5.7 | length 84.5
  Top Layer w0.254: v1@41.465,10.274 D211.1@42.202,9.538 ; v1@43.599,10.274 D212.1@44.336,9.538 ; v1@45.733,10.274 D213.1@46.469,9.538 ; v1@47.866,10.274 D214.1@48.603,9.538 ; v1@50,10.274 D215.1@50.736,9.538 ; v1@52.133,10.274 D216.1@52.87,9.538 ; v1@54.267,10.274 D217.1@55.004,9.538 ; v1@56.401,10.274 D218.1@57.137,9.538 ; v1@58.534,10.274 D219.1@59.271,9.538 ; v1@60.668,10.274 D220.1@61.404,9.538 ; v1@62.801,10.274 D221.1@63.538,9.538 ; v1@64.935,10.274 D222.1@65.672,9.538 ; v1@67.069,10.274 D223.1@67.805,9.538 ; v1@69.202,10.274 D224.1@69.939,9.538 ; D14.2@70.575,38.76 D29.2@70.575,36.638 D44.2@70.575,34.505 D59.2@70.575,32.371 D74.2@70.575,30.237 D89.2@70.575,28.104 D104.2@70.575,25.97 D119.2@70.575,23.837 D134.2@70.575,21.703 D149.2@70.575,19.569 D164.2@70.575,17.436 D179.2@70.575,15.302 D194.2@70.575,13.169 70.575,11.023 v1(71.336,10.286) ; v1@71.336,10.274 D225.1@72.072,9.538 ; D225.1@72.072,9.55 72.072,8.483 72.709,7.823 D240.2@72.709,6.756
  Int2 (PWR) w0.3: J5.7@63.856,3.581 63.856,9.207 v1(64.935,10.286)
  Bottom Layer w0.254: v1(41.465,10.286) v1(43.599,10.286) v1(45.733,10.286) v1(47.866,10.286) v1(50,10.286) v1(52.133,10.286) v1(54.267,10.286) v1(56.401,10.286) v1(58.534,10.286) v1(60.668,10.286) v1(62.801,10.286) v1(64.935,10.286) v1(67.069,10.286) v1(69.202,10.286) v1(71.336,10.286)
PIN16: D15.2 D30.2 D45.2 D60.2 D75.2 D90.2 D105.2 D120.2 D135.2 D150.2 D165.2 D180.2 D195.2 D210.2 D225.2 D226.1 D227.1 D228.1 D229.1 D230.1 D231.1 D232.1 D233.1 D234.1 D235.1 D236.1 D237.1 D238.1 D239.1 D240.1 J5.8 | length 83.4
  Top Layer w0.254: v1@41.465,8.141 D226.1@42.202,7.404 ; v1@43.599,8.141 D227.1@44.336,7.404 ; v1@45.733,8.141 D228.1@46.469,7.404 ; v1@47.866,8.141 D229.1@48.603,7.404 ; v1@50,8.141 D230.1@50.736,7.404 ; v1@52.133,8.141 D231.1@52.87,7.404 ; v1@54.267,8.141 D232.1@55.004,7.404 ; v1@56.401,8.141 D233.1@57.137,7.404 ; v1@58.534,8.141 D234.1@59.271,7.404 ; v1@60.668,8.141 D235.1@61.404,7.404 ; v1@62.801,8.141 D236.1@63.538,7.404 ; v1@64.935,8.141 D237.1@65.672,7.404 ; v1@67.069,8.141 D238.1@67.805,7.404 ; v1@69.202,8.141 D239.1@69.939,7.404 ; v1@71.336,8.141 D240.1@72.072,7.404 ; D15.2@72.709,38.76 D30.2@72.709,36.638 D45.2@72.709,34.505 D60.2@72.709,32.371 D75.2@72.709,30.237 D90.2@72.709,28.104 D105.2@72.709,25.97 D120.2@72.709,23.837 D135.2@72.709,21.703 D150.2@72.709,19.569 D165.2@72.709,17.436 D180.2@72.709,15.302 D195.2@72.709,13.169 D210.2@72.709,11.035 72.709,8.889 v1(73.469,8.153)
  Int2 (PWR) w0.3: J5.8@66.396,3.581 66.396,7.411 67.069,8.085 v1(67.069,8.153)
  Bottom Layer w0.254: v1(41.465,8.153) v1(43.599,8.153) v1(45.733,8.153) v1(47.866,8.153) v1(50,8.153) v1(52.133,8.153) v1(54.267,8.153) v1(56.401,8.153) v1(58.534,8.153) v1(60.668,8.153) v1(62.801,8.153) v1(64.935,8.153) v1(67.069,8.153) v1(69.202,8.153) v1(71.336,8.153) v1(73.469,8.153)
PROG: R2.2 U1.5 | length 1.7
  Top Layer w0.3: U1.5@15.652,35.707 15.659,35.713 17.317,35.713 R2.2@17.323,35.72
PWR_LED_K: PWR.2 R5.2 | length 2.7
  Top Layer w0.3: PWR.2@12.107,19.736 12.555,19.288 R5.2@12.555,17.247
STAT: J4.6 R3.1 U1.1 U3.10 | length 55.6
  Top Layer w0.3: v2(10.707,36.627) 10.707,36.437 11.437,35.707 U1.1@12.852,35.707 ; R3.1@13.455,28.702 13.538,28.785 v2(13.538,31.267) ; v2(16.18,12.878) 16.154,12.903 16.154,14.326 15.291,15.189 15.291,15.823 15.78,16.312 15.78,17.768 19.211,21.199 19.211,21.438 ; v2(16.18,21.438) 19.211,21.438 ; U3.10@21.231,21.716 19.489,21.716 19.211,21.438
  Bottom Layer w0.3: v2(10.707,36.627) 10.896,36.627 11.127,36.857 15.217,36.857 15.392,36.682 15.392,32.715 14.079,31.401 13.672,31.401 v2(13.538,31.267) 13.548,31.257 13.548,30.216 15.646,28.118 15.646,25.336 14.63,24.32 14.63,21.613 14.806,21.438 v2(16.18,21.438) ; v2(16.18,12.878) 16.739,12.319 16.739,8.401 16.914,8.225 21.086,8.225 J4.6@22.301,7.01
STATUS_LED_A: LED.1 R7.1 | length 2.8
  Top Layer w0.3: R7.1@23.97,36.627 26.035,36.627 LED.1@26.568,37.16
STM_BOOT0: R8.2 U3.44 | length 5.1
  Top Layer w0.3: R8.2@24.384,32.588 24.409,32.588 24.661,32.336 U3.44@24.661,27.646
STM_JTDI: J4.1 U3.38 | length 40.2
  Top Layer w0.3: U3.38@27.661,27.646 27.661,29.961 28.016,30.316 v2(28.016,31.255)
  Int2 (PWR) w0.3: J4.1@9.601,7.01 11.608,9.017 11.608,22.703 18.914,30.009 26.77,30.009 v2(28.016,31.255)
STM_NRST: C5.2 R1.1 RESET.2 U3.7 | length 28.6
  Top Layer w0.3: C5.2@13.655,23.139 16.283,23.139 16.535,23.391 16.535,24.494 R1.1@16.632,24.591 ; R1.1@16.535,24.594 16.568,24.562 17.969,24.562 18.249,24.282 18.906,24.282 19.973,23.216 U3.7@21.231,23.216
  Int2 (PWR) w0.3: v2(17.78,24.562) 17.969,24.562 18.237,24.294 18.977,24.294 27.572,24.294 RESET.2@34.061,17.805
STM_PA2: J4.7 U3.12 | length 23.6
  Top Layer w0.3: v2(17.145,13.97) 17.12,13.995 17.12,17.831 20.004,20.716 U3.12@21.231,20.716
  Bottom Layer w0.3: v2(17.145,13.97) 17.145,8.812 17.321,8.636 24.665,8.636 24.841,8.46 J4.7@24.841,7.01
STM_PA8: J4.8 U3.29 | length 57.3
  Top Layer w0.3: U3.29@29.591,22.716 32.313,22.716 v2(33.198,21.831)
  Int2 (PWR) w0.3: 21.603,8.756 cw(c21.387,9.474) 21.349,8.725 18.315,8.876 ccw(c18.295,8.477) 18.295,8.877 16.486,8.877 15.851,9.512 14.101,9.512 13.716,9.898 13.716,21.844 19.881,28.009 28.531,28.009 31.471,25.07 31.471,22.006 31.646,21.831 v2(33.198,21.831) ; 21.604,8.756 cw(c21.691,8.469) 21.716,8.768 22.518,8.701 ccw(c22.581,9.449) 22.615,8.7 23.162,8.725 ccw(c23.148,9.024) 23.36,8.812 23.501,8.953 25.439,8.953 J4.8@27.381,7.01
STM_PA11: J1.4 U3.32 | length 41.4
  Top Layer w0.3: U3.32@29.591,24.216 32.165,24.216 32.438,24.488 33.39,24.488 34.13,23.749 v2(35.282,23.749)
  Int2 (PWR) w0.3: J1.4@17.221,39.903 18.436,41.118 27.884,41.118 28.706,40.296 32.799,40.296 36.735,36.36 36.735,25.128 35.357,23.749 v2(35.282,23.749)
STM_PA12: J1.5 U3.33 | length 39.6
  Top Layer w0.3: U3.33@29.591,24.716 32.099,24.716 32.272,24.888 33.862,24.888 34.161,24.588 v2(34.351,24.588)
  Bottom Layer w0.3: J1.5@19.761,39.903 21.082,41.224 29.921,41.224 30.849,40.296 36.172,40.296 36.347,40.121 36.347,25.432 35.504,24.588 v2(34.351,24.588)
STM_PC13: LED.2 U3.2 | length 24.4
  Top Layer w0.3: v2(19.304,25.044) 19.976,25.716 U3.2@21.231,25.716 ; LED.2@28.668,37.16 29.743,36.085 v2(29.743,34.874)
  Bottom Layer w0.3: v2(19.304,25.044) 19.304,32.588 21.285,34.569 22.987,34.569 23.966,35.548 24.726,35.548 25.4,34.874 v2(29.743,34.874)
STM_SWCLK: J4.3 U3.37 | length 45.5
  Top Layer w0.3: U3.37@28.161,27.646 28.161,29.66 v2(29.057,30.556)
  Int2 (PWR) w0.3: J4.3@14.681,7.01 14.574,6.903 14.574,5.971 14.398,5.795 11.223,5.795 10.926,6.092 10.926,7.514 12.04,8.627 12.04,22.569 19.08,29.609 27.977,29.609 28.924,30.556 v2(29.057,30.556)
STM_SWDIO: J4.2 U3.34 | length 49.5
  Top Layer w0.3: U3.34@29.591,25.216 32.034,25.216 32.156,25.338 35.004,25.338 35.396,25.73 v2(35.585,25.73)
  Int2 (PWR) w0.3: J4.2@12.141,7.01 12.384,7.253 12.384,7.759 12.446,7.821 12.446,22.41 19.246,29.209 29.447,29.209 33.318,25.338 34.805,25.338 34.81,25.343 35.06,25.343 35.447,25.73 v2(35.585,25.73)
STM_USART1_RX: J4.5 U3.31 | length 53.9
  Top Layer w0.3: U3.31@29.591,23.716 32.231,23.716 32.603,24.088 33.225,24.088 34.676,22.637 v2(34.702,22.637)
  Int2 (PWR) w0.3: J4.5@19.761,7.01 18.295,8.477 16.321,8.477 15.685,9.112 13.644,9.112 13.259,9.498 13.259,22.022 19.646,28.409 28.868,28.409 31.902,25.375 31.902,22.813 32.127,22.588 34.653,22.588 v2(34.702,22.637)
STM_USART1_TX: J4.4 U3.30 | length 47.9
  Top Layer w0.3: U3.30@29.591,23.216 29.601,23.226 32.801,23.226 v2(32.914,23.338)
  Int2 (PWR) w0.3: J4.4@17.221,7.01 15.519,8.712 13.028,8.712 12.852,8.888 12.852,22.25 19.411,28.809 29.128,28.809 32.914,25.023 v2(32.914,23.338)
SWITCH: BAT1.1 SW_BAT.3 | length 6.9
  Bottom Layer w0.3: SW_BAT.3@4.572,10.541 6.375,12.344 6.375,14.023 6.551,14.199 8.922,14.199 BAT1.1@8.966,14.243
VBAT: C7.2 STM_PWR.4 SW_BAT.2 U1.3 | length 35.9
  Top Layer w0.3: STM_PWR.4@4.572,33.833 4.592,33.813 10.242,33.813 C7.2@10.262,33.793 10.269,33.8 12.845,33.8 U1.3@12.852,33.807
  Bottom Layer w0.3: SW_BAT.2@4.572,8.001 3.342,9.231 3.342,17.811 4.204,18.673 4.204,28.052 3.342,28.914 3.342,32.603 STM_PWR.4@4.572,33.833
VBUS: C6.2 J1.8 PWR_IN1.VBUS STM_PWR.2 U1.4 | length 56.2
  Top Layer w0.3: STM_PWR.2@4.572,38.913 4.669,38.913 5.38,38.202 21.742,38.202 ; PWR_IN1.VBUS@7.674,20.962 7.524,21.112 7.1,21.112 6.854,21.359 6.854,25.366 7.1,25.612 7.524,25.612 PWR_IN1.VBUS@7.674,25.762 7.824,25.912 10.34,25.912 10.516,26.088 10.516,31.879 10.691,32.055 15.088,32.055 ; C6.2@15.088,30.926 15.088,32.055 ; J1.8@27.381,39.903 25.679,38.202 21.742,38.202 ; 15.088,32.055 15.496,32.055 15.672,32.231 15.672,33.788 U1.4@15.652,33.807 20.345,33.807 21.742,35.204 21.742,38.202
VCC3V3: BOOT0.2 C1.2 C2.2 C3.2 C4.2 C8.2 C11.2 C12.2 C13.2 C14.2 CHG.1 J1.6 PWR.1 R1.2 R7.2 U2.5 U3.1 U3.9 U3.VDD U4.8 U4.13 | length 60.2
  Top Layer w0.2: v2(19.152,16.307) 19.228,16.383 21.549,16.383 21.666,16.266 21.666,15.578 C14.2@21.699,15.545 ; C14.2@21.719,15.545 22.143,15.121 U4.13@22.143,14.046 ; U4.8@22.643,11.796 23.258,11.796 24.435,10.619 C11.2@24.435,10.599 ; v2(23.546,10.287) 24.529,10.287 C11.2@24.689,10.447
  Top Layer w0.3: C8.2@14.289,9.5 15.926,9.5 15.977,9.55 v2(15.977,10.566) 15.938,10.605 15.938,11.271 15.762,11.447 U2.5@14.539,11.447 ; v2(14.58,27.889) 14.58,27.711 14.207,27.339 CHG.1@14.207,26.289 16.36,26.289 16.535,26.113 R1.2@16.535,25.494 18.666,25.494 18.747,25.576 18.747,26.08 C13.2@18.905,26.238 ; v2(15.85,20.218) 15.806,20.218 15.324,19.736 PWR.1@14.207,19.736 14.249,19.778 14.249,22.042 14.425,22.218 C3.2@18.898,22.218 C3.2@18.898,22.218 U3.9@21.23,22.217 ; v2(20.396,30.759) 20.402,30.765 21.458,30.765 21.633,30.589 C1.2@21.633,29.642 21.621,29.629 19.331,29.629 19.331,29.579 18.905,29.153 C13.2@18.905,26.238 ; U3.1@21.231,26.216 21.221,26.226 18.918,26.226 C13.2@18.905,26.238 ; C1.2@21.653,29.642 21.863,29.432 21.863,29.063 22.661,28.266 U3.VDD@22.661,27.646 ; v2(22.631,35.357) 22.631,35.47 23.063,35.902 23.063,36.502 23.07,36.509 R7.2@23.07,36.627 ; U3.VDD@28.161,19.286 28.161,17.736 C2.2@28.372,17.526 ; C2.2@28.372,17.526 28.41,17.488 28.41,14.668 v2(28.448,14.63) ; U3.VDD@29.591,26.216 30.211,26.216 30.869,26.873 31.539,26.873 C12.2@31.57,26.904 ; C12.2@31.572,26.906 31.572,26.926 31.362,27.136 31.342,27.136 30.963,27.516 30.963,29.593 31.138,29.769 33.236,29.769 33.896,29.108 BOOT0.2@34.061,29.108 ; U3.9@21.23,22.217 U3.9@21.231,22.216
VCC5V: C9.2 J1.7 STM_PWR.3 U2.1 U2.3 | length 56.5
  Top Layer w0.3: STM_PWR.3@4.572,36.373 5.692,37.493 20.826,37.493 v2(20.93,37.389) ; C9.2@12.051,15.698 12.639,15.11 U2.3@12.639,13.648 12.691,13.596 12.691,12.861 13.056,12.497 14.199,12.497 14.407,12.705 14.407,13.516 U2.1@14.539,13.648 ; U2.1@14.539,13.716 14.539,15.637 15.355,16.453 15.355,18.022 17.205,19.872 17.205,20.583 v2(17.221,20.599)
  Bottom Layer w0.3: v2(17.221,20.599) 17.221,22.073 16.046,23.247 16.046,29.991 20.93,34.874 v2(20.93,37.389) 24.665,37.389 24.841,37.565 J1.7@24.841,39.903
pads on no net: BOOT0.1 BOOT0.5 PWR_IN1. PWR_IN1.A6 PWR_IN1.A7 PWR_IN1.A8 PWR_IN1.B6 PWR_IN1.B7 PWR_IN1.B8 RESET.1 RESET.4 RESET.5 STM_PWR.1 STM_PWR.5 SW_BAT.1 SW_BAT.4 SW_BAT.5 U3.3 U3.4 U3.5 U3.6 U3.13 U4.1 U4.2 U4.3 U4.4 U4.5 U4.6 U4.7 U4.14 U4.15 U4.16 U4.17 U4.19 U4.21

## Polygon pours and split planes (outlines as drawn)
GND on Top Layer "GND_L01_P008" (solid, pour order 8): 8.23,20.447 7.087,20.447 7.087,19.888 5.791,19.888 5.791,18.364 8.23,18.364
GND on Top Layer "GND_L01_P007" (solid, pour order 7): 7.087,26.264 7.087,26.899 5.817,26.899 5.817,28.372 8.23,28.372 8.23,26.264 7.747,26.264
GND on Int1 (GND) "GND_L02_P001" (solid, pour order 1): 2.972,2.057 2.997,2.083 2.997,44.856 35.636,44.856 35.636,4.064 35.611,4.039 35.611,2.057 29.261,2.057
VCC3V3 on Int2 (PWR) "VCC3V3_L03_P009" (solid, pour order 9): 35.636,4.851 6.274,4.851 6.274,42.088 35.636,42.088

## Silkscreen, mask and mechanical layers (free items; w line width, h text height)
Top Overlay:
  drawing of 278 lines, arcs and shapes, not listed
  text "Axelor" at 15.196,16.987 h3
